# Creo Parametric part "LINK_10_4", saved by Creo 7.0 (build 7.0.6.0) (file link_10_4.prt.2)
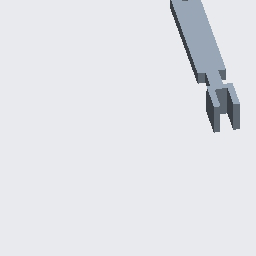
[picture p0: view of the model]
Units: millimeter Newton Second (mmNs); MM, TONNE, SECS

Created from: XX_MMNS_PART_SOLID_ABS.PRT

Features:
  1. datum plane "RIGHT"
  2. datum plane "TOP"
  3. datum plane "FRONT"
  4. coordinate system
  5. extrusion "Extrude 1"
  6. extruded cut "Extrude 2"
  7. extrusion "Extrude 3"
  8. extrusion "Extrude 4"
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
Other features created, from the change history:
  extruded cut "Extrude 5"

Surfaces: 16 plane, 2 cylinder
